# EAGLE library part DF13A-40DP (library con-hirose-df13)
DF13-40DP Double row, 1.25mm Pitch Miniature Crimping Connector.
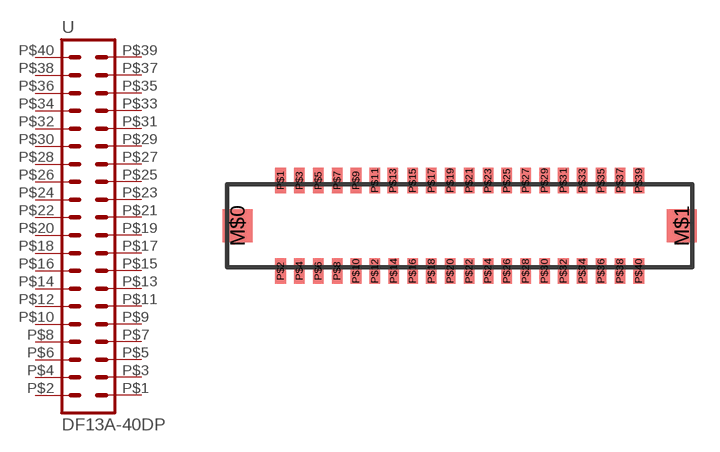
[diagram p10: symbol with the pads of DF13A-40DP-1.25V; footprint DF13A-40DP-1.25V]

Designator prefix -

## DF13A-40DPDP-1.25V  [DF13A-40DP-1.25V]
P$1  1  pas
P$2  2  pas
P$3  3  pas
P$4  4  pas
P$5  5  pas
P$6  6  pas
P$7  7  pas
P$8  8  pas
P$9  9  pas
P$10  10  pas
P$11  11  pas
P$12  12  pas
P$13  13  pas
P$14  14  pas
P$15  15  pas
P$16  16  pas
P$17  17  pas
P$18  18  pas
P$19  19  pas
P$20  20  pas
P$21  21  pas
P$22  22  pas
P$23  23  pas
P$24  24  pas
P$25  25  pas
P$26  26  pas
P$27  27  pas
P$28  28  pas
P$29  29  pas
P$30  30  pas
P$31  31  pas
P$32  32  pas
P$33  33  pas
P$34  34  pas
P$35  35  pas
P$36  36  pas
P$37  37  pas
P$38  38  pas
P$39  39  pas
P$40  40  pas

## Footprint DF13A-40DP-1.25V (pad centres in mm)
Double Row Straight Pin Header (SMT)
smd 2 x 2.2: M$0 -14.725,0; M$1 14.725,0
smd 0.7 x 1.7: P$1 -11.875,3; P$2 -11.875,-3; P$3 -10.625,3; P$4 -10.625,-3; P$5 -9.375,3; P$6 -9.375,-3; P$7 -8.125,3; P$8 -8.125,-3; P$9 -6.875,3; P$10 -6.875,-3; P$11 -5.625,3; P$12 -5.625,-3; P$13 -4.425,3; P$14 -4.375,-3; P$15 -3.125,3; P$16 -3.125,-3; P$17 -1.875,3; P$18 -1.875,-3; P$19 -0.625,3; P$20 -0.625,-3; P$21 0.625,3; P$22 0.625,-3; P$23 1.875,3; P$24 1.875,-3; P$25 3.125,3; P$26 3.125,-3; P$27 4.375,3; P$28 4.375,-3; P$29 5.625,3; P$30 5.625,-3; P$31 6.875,3; P$32 6.875,-3; P$33 8.125,3; P$34 8.125,-3; P$35 9.375,3; P$36 9.375,-3; P$37 10.625,3; P$38 10.625,-3; P$39 11.875,3; P$40 11.875,-3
